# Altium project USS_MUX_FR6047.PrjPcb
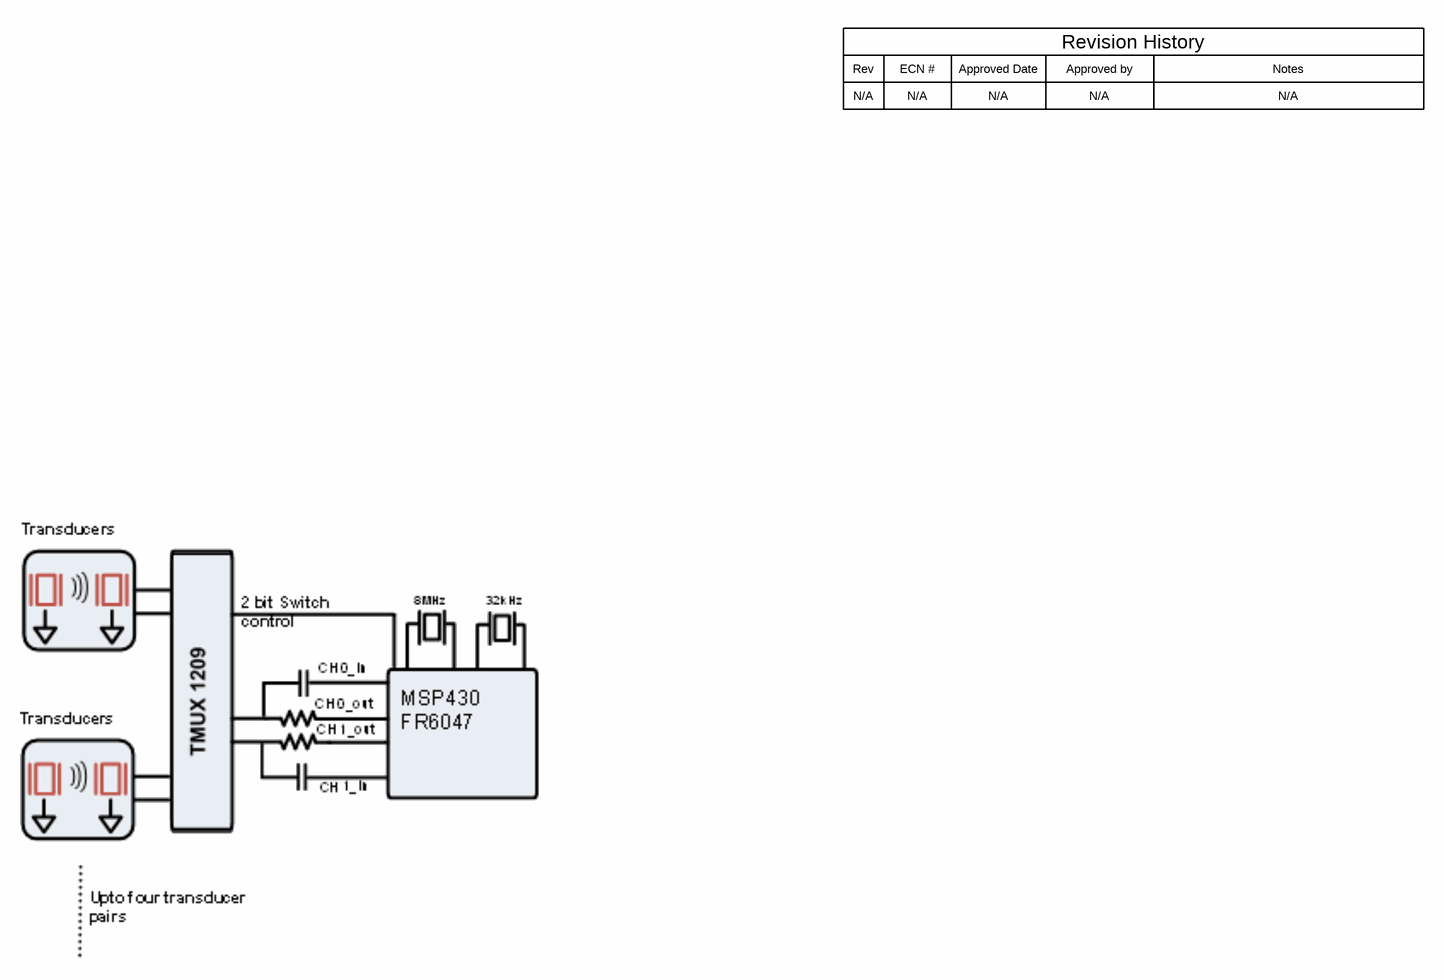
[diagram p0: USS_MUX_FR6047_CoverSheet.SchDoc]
CopyrightYear: 2019; PCB_Layout: Eddie LaCost; PCB_Rev: E1; PRJ_Customer: Public Release; PRJ_Engineer: Eddie LaCost; PRJ_Number: USS MUX FR6047; PRJ_Title: USS MUX FR6047; SCH_Rev: E1; TechSupport: http://www.ti.com/support; TID: N/A
3 sheets, 38 parts. Net scope: global (net labels, ports and power ports of the same name join across sheets).
Board file: USS_MUX_FR6047_PCB.PcbDoc
Sheets:
  USS_MUX_FR6047_CoverSheet.SchDoc
  USS_MUX_FR6047.SchDoc
  USS_MUX_FR6047_Hardware.SchDoc

## Sheet USS_MUX_FR6047_CoverSheet.SchDoc
size 431 x 279 mm; Date: Not shown in title block; ApprovedBy: Not shown in title block; CheckedBy: Not shown in title block; Author: Not shown in title block; CompanyName: Not shown in title block; Engineer: Not shown in title block; Organization: Not shown in title block; Address1: Not shown in title block; Address2: Not shown in title block; Address3: Not shown in title block; Address4: Not shown in title block; DocumentNumber: 1; Revision: Use project parameter SCH_Rev; SheetNumber: 1; SheetTotal: 3; PageSetup: Record=PageOptions¦CenterHorizontal=True¦CenterVertical=True¦PrintScale=1.00¦XCorrection=1.00¦YCorrection=1.00¦PrintKind=0¦BorderSize=5000000¦LeftOffset=0¦BottomOffset=0¦Orientation=2¦PaperLength=1000¦PaperWidth=1000¦Scale=100¦PaperSource=15¦PrintQuality=600¦MediaType=1¦DitherType=10¦PaperKind=Letter¦PrintScaleMode=1

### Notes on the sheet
- Rev
- N/A
- ECN #
- Approved Date
- Approved by
- Revision History
- Notes

## Sheet USS_MUX_FR6047.SchDoc
size 431 x 279 mm; Date: Not shown in title block; ApprovedBy: Not shown in title block; CheckedBy: Not shown in title block; Author: Not shown in title block; CompanyName: Not shown in title block; Engineer: Not shown in title block; Organization: Not shown in title block; Address1: Not shown in title block; Address2: Not shown in title block; Address3: Not shown in title block; Address4: Not shown in title block; DocumentNumber: 1; Revision: Use project parameter SCH_Rev; SheetNumber: 2; SheetTotal: 3; PageSetup: Record=PageOptions¦CenterHorizontal=True¦CenterVertical=True¦PrintScale=1.00¦XCorrection=1.00¦YCorrection=1.00¦PrintKind=0¦BorderSize=5000000¦LeftOffset=0¦BottomOffset=0¦Orientation=2¦PaperLength=1000¦PaperWidth=1000¦Scale=100¦PaperSource=15¦PrintQuality=600¦MediaType=1¦DitherType=10¦PaperKind=Letter¦PrintScaleMode=1
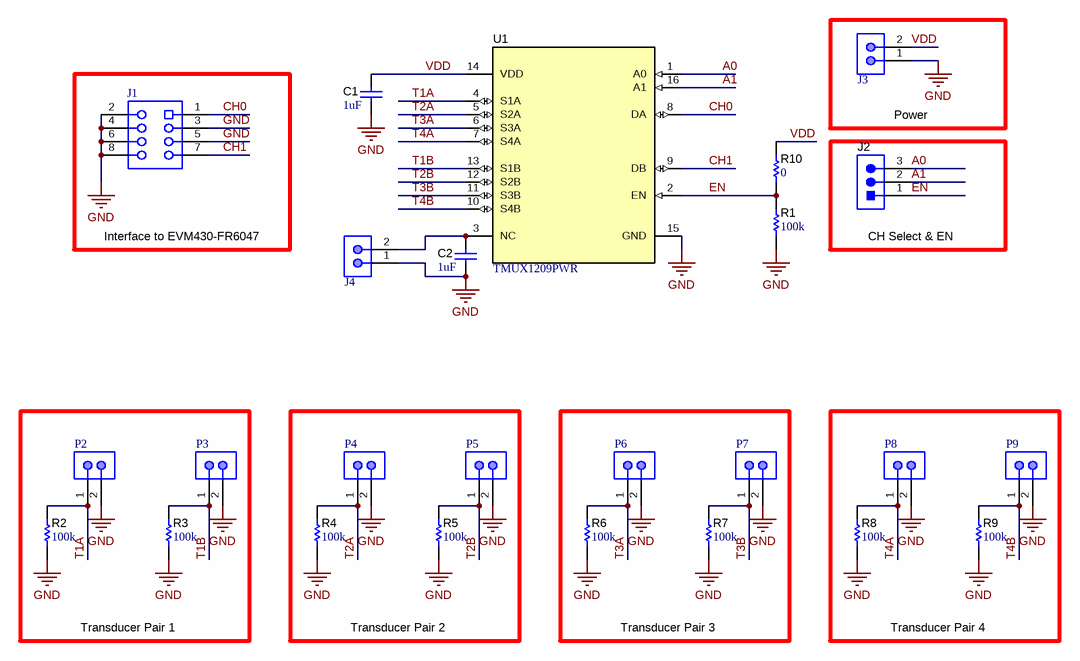
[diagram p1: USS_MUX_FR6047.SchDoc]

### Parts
C1  ValueDisplayed: 1uF  [0603]  (hidden comment: GRM188R61A105KA61D)
C2  ValueDisplayed: 1uF  [0603]  (hidden comment: GRM188R61A105KA61D)
J1  PPPC042LFBN-RC  [CONN_PPPC042LFBN-RC]  (value not drawn)
J2  PBC03SAAN  [PBC03SAAN]  (value not drawn)
J3  613 002 111 21  [WE-61300211121_V]  (value not drawn)
J4  613 002 111 21  [WE-61300211121_V]  (value not drawn)
P2  613 002 111 21  [WE-61300211121_V]  (value not drawn)
P3  613 002 111 21  [WE-61300211121_V]  (value not drawn)
P4  613 002 111 21  [WE-61300211121_V]  (value not drawn)
P5  613 002 111 21  [WE-61300211121_V]  (value not drawn)
P6  613 002 111 21  [WE-61300211121_V]  (value not drawn)
P7  613 002 111 21  [WE-61300211121_V]  (value not drawn)
P8  613 002 111 21  [WE-61300211121_V]  (value not drawn)
P9  613 002 111 21  [WE-61300211121_V]  (value not drawn)
R1  ValueDisplayed: 100k  [0402]  (hidden comment: ERJ-2GEJ104X)
R2  ValueDisplayed: 100k  [0402]  (hidden comment: ERJ-2GEJ104X)
R3  ValueDisplayed: 100k  [0402]  (hidden comment: ERJ-2GEJ104X)
R4  ValueDisplayed: 100k  [0402]  (hidden comment: ERJ-2GEJ104X)
R5  ValueDisplayed: 100k  [0402]  (hidden comment: ERJ-2GEJ104X)
R6  ValueDisplayed: 100k  [0402]  (hidden comment: ERJ-2GEJ104X)
R7  ValueDisplayed: 100k  [0402]  (hidden comment: ERJ-2GEJ104X)
R8  ValueDisplayed: 100k  [0402]  (hidden comment: ERJ-2GEJ104X)
R9  ValueDisplayed: 100k  [0402]  (hidden comment: ERJ-2GEJ104X)
R10  ValueDisplayed: 0  [0603]  (hidden comment: MCR03EZPJ000)
U1  TMUX1209PWR  [PW0016A_N]

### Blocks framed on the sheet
Power: J3
Interface to EVM430-FR6047: J1
CH Select & EN: J2
Transducer Pair 1: P2 P3 R2 R3
Transducer Pair 2: P4 P5 R4 R5
Transducer Pair 3: P6 P7 R6 R7
Transducer Pair 4: P8 P9 R8 R9

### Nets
GND: C1.2 C2.2 J1.2 J1.3 J1.4 J1.5 J1.6 J1.8 J3.1 J4.1 P2.2 P3.2 P4.2 P5.2 P6.2 P7.2 P8.2 P9.2 R1.1 R2.1 R3.1 R4.1 R5.1 R6.1 R7.1 R8.1 R9.1 U1.15(GND)
A0: J2.3 U1.1(A0)
A1: J2.2 U1.16(A1)
CH0: J1.1 U1.8(DA)
CH1: J1.7 U1.9(DB)
EN: J2.1 R1.2 R10.1 U1.2(EN)
T1A: P2.1 R2.2 U1.4(S1A)
T1B: P3.1 R3.2 U1.13(S1B)
T2A: P4.1 R4.2 U1.5(S2A)
T2B: P5.1 R5.2 U1.12(S2B)
T3A: P6.1 R6.2 U1.6(S3A)
T3B: P7.1 R7.2 U1.11(S3B)
T4A: P8.1 R8.2 U1.7(S4A)
T4B: P9.1 R9.2 U1.10(S4B)
VDD: C1.1 J3.2 R10.2 U1.14(VDD)
NetC2_1: C2.1 J4.2 U1.3(NC)

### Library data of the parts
C1 C2 = CMP-0007317-5: CAP, CERM, 1 uF, 10 V, +/- 10%, X5R, 0603; Manufacturer: MuRata; TaMin_C: -55°C; Polarized: N; SizeAreaWB_mm2: 4.68; Value1: Unknown; U/M: EA; Value: 1uF; TaMax_C: 85°C; SizeZ_mm: 1; SizeX_mm: 1.6; SizeY_mm: 0.8; Value2: 10V; SizeArea_mm2: 1.28; Cap_F: 1µF; AEC Category: Q200
J1 = CMP-0054629-2: Connector, Receptacle, 100mil, 4x2, Gold plated, TH; Manufacturer: Sullins Connector Solutions; CompType: Socket Strip
J2 = CMP-0002334-1: Header, 100mil, 3x1, Gold, TH; Manufacturer: Sullins Connector Solutions; CNHeader: TRUE; Green_Lifecycle: Not Set; Green_REACh: Incomplete; CT: FALSE
J3 J4 P2-P9 = CMP-1712-00002-2: Male Header, Pitch 2.54 mm, 1 x 2 Position, Height 8.54 mm, Tail Length 3 mm, -40 to 105 degC, RoHS, Bulk
R1-R9 = CMP-0026995-2: RES, 100 k, 5%, 0.1 W, AEC-Q200 Grade 0, 0402; Manufacturer: Panasonic; Power_W: 100mW; TempCo: 200 ppm/C; U/M: EA; Value: 100k; EIA_Code: E24; SizeX_mm: 1; SizeY_mm: 0.5; SizeZ_mm: 0.6; Value2: 0.1W; AEC Qualified: Y; VDC_V: 50V; AEC Grade: 0; AEC Category: Q200
R10 = CMP-0025883-3: RES, 0, 5%, 0.1 W, 0603; Manufacturer: Rohm; Power_W: 100mW; TempCo: 400 ppm/C; Value_Code: 0000; U/M: EA; Value: 0; EIA_Code: E24; SizeX_mm: 1.6; SizeY_mm: 0.8; SizeZ_mm: 1; Value2: 0.1W; SizeArea_mm2: 1.28; AEC Qualified: N; VDC_V: 50V; AEC Category: Q200
U1 = CMP-0860324-1: 5-V Bidirectional 4:1, 2-Channel Multiplexer, PW0016A (TSSOP-16); Alternate Manufacturer: Texas Instruments; SizeZ_mm: 1.2; Rating: Catalog; CompType: IC; AEC Qualified: N; SizeArea_mm2: 32; SizeY_mm: 5; AEC Category: Q200; SizeX_mm: 6.4; SizeAreaWB_mm2: 58.8

## Sheet USS_MUX_FR6047_Hardware.SchDoc
size 431 x 279 mm; Date: Not shown in title block; ApprovedBy: Not shown in title block; CheckedBy: Not shown in title block; Author: Not shown in title block; CompanyName: Not shown in title block; Engineer: Not shown in title block; Organization: Not shown in title block; Address1: Not shown in title block; Address2: Not shown in title block; Address3: Not shown in title block; Address4: Not shown in title block; DocumentNumber: 1; Revision: Use project parameter SCH_Rev; SheetNumber: 3; SheetTotal: 3; PageSetup: Record=PageOptions¦CenterHorizontal=True¦CenterVertical=True¦PrintScale=1.00¦XCorrection=1.00¦YCorrection=1.00¦PrintKind=0¦BorderSize=5000000¦LeftOffset=0¦BottomOffset=0¦Orientation=2¦PaperLength=1000¦PaperWidth=1000¦Scale=100¦PaperSource=15¦PrintQuality=600¦MediaType=1¦DitherType=10¦PaperKind=Letter¦PrintScaleMode=1
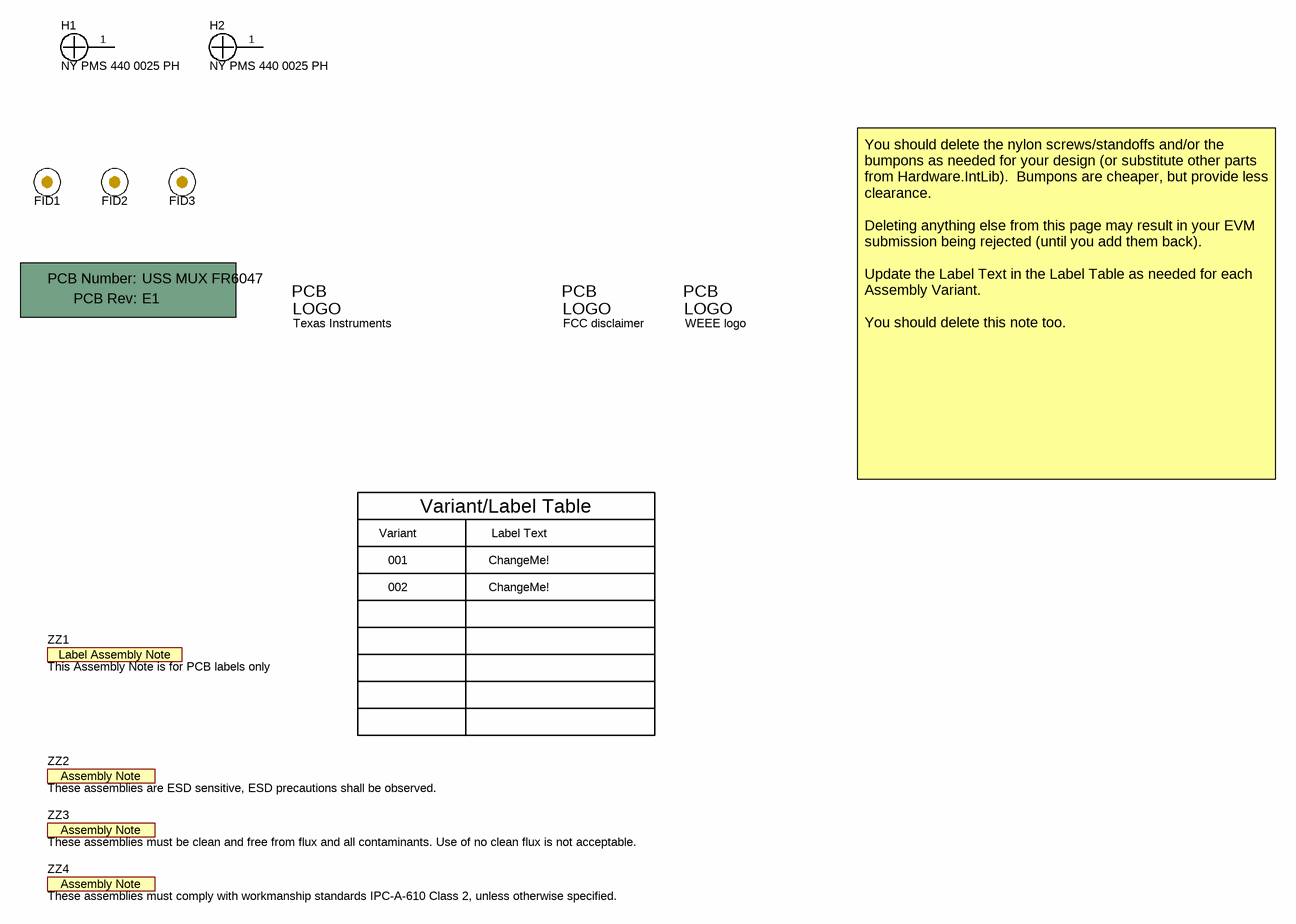
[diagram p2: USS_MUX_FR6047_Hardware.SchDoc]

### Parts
!PCB  Printed Circuit Board  (value not drawn)  (mechanical)
FID1  Fiducial  [Fiducial10-20]  (value not drawn)
FID2  Fiducial  [Fiducial10-20]  (value not drawn)
FID3  Fiducial  [Fiducial10-20]  (value not drawn)
H1  NY PMS 440 0025 PH  [NY PMS 440 0025 PH]
H2  NY PMS 440 0025 PH  [NY PMS 440 0025 PH]
Logo1  Texas Instruments  [TI_Stacked_Overlay_Small]  (no BOM)
Logo3  FCC disclaimer  [FCC_disclaimer]  (no BOM)
Logo4  WEEE logo  [WEEE_Minimum]  (no BOM)
ZZ1  This Assembly Note is for PCB labels only  [AssemblyNoteLabel]  (no BOM)
ZZ2  These assemblies are ESD sensitive, ESD precautions shall be observed.  [AssemblyNote]  (no BOM)
ZZ3  These assemblies must be clean and free from flux and all contaminants. Use of no clean flux is not acceptable.  [AssemblyNote]  (no BOM)
ZZ4  These assemblies must comply with workmanship standards IPC-A-610 Class 2, unless otherwise specified.  [AssemblyNote]  (no BOM)

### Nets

Not connected (* = marked no-connect by the designer): H1 1; H2 1

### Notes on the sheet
- Variant
- Variant/Label Table
- Label Text
- You should delete the nylon screws/standoffs and/or the bumpons as needed for your design (or substitute other parts from Hardware.IntLib).  Bumpons are cheaper, but provide less clearance.
  Deleting anything else from this page may result in your EVM submission being rejected (until you add them back).
  Update the Label Text in the Label Table as needed for each Assembly Variant.
  You should delete this note too.
- 001
- 002
- ChangeMe!

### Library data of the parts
!PCB = CMP-0003618-2: Manufacturer: Any; PartNumber: USS MUX FR6047
FID1-FID3 = CMP-0077181-1: Fiducial mark.  There is nothing to buy or mount.
H1 H2 = CMP-0003617-1: Machine Screw, Round, #4-40 x 1/4, Nylon, Philips panhead; Manufacturer: B&F Fastener Supply; CompType: Hardware
Logo1 = CMP-0074838-1: Texas Instrument Corporate Signature; SymbolCreator: a0412235; Lib Reference: TI_Logo; Library Reference: Logo
Logo3 = CMP-0074847-1: FCC_disclaimer; Library Reference: Logo
Logo4 = CMP-0074769-1
ZZ1 = CMP-0003616-3
ZZ2 = CMP-0077236-1
ZZ3 = CMP-0077237-1
ZZ4 = CMP-0077238-1

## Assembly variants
001: not fitted FID1 FID2 FID3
